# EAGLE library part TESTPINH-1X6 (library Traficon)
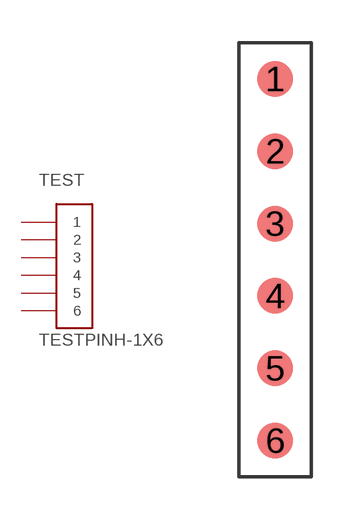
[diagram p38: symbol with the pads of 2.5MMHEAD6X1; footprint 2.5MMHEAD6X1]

Designator prefix TEST

## TESTPINH-1X6  [2.5MMHEAD6X1]
1  1  pas
2  2  pas
3  3  pas
4  4  pas
5  5  pas
6  6  pas

## Footprint 2.5MMHEAD6X1 (pad centres in mm)
smd 1.27 x 1.27: 1 0,6.35; 2 0,3.81; 3 0,1.27; 4 0,-1.27; 5 0,-3.81; 6 0,-6.35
